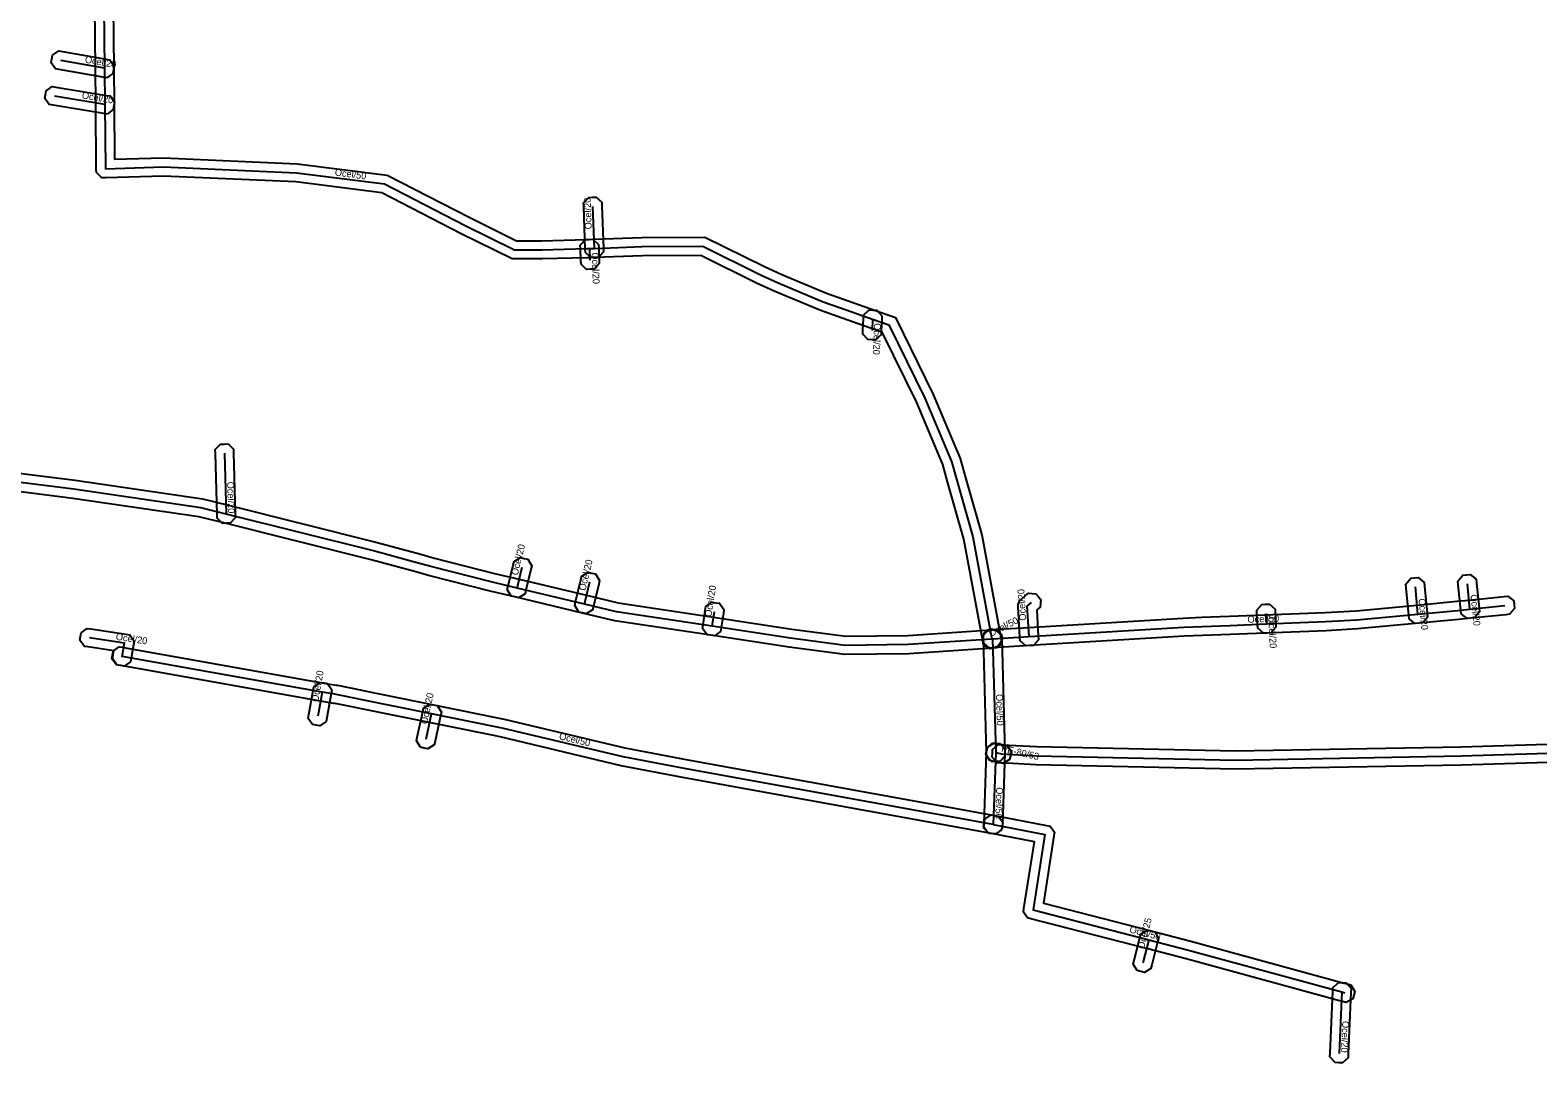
# Model space of a CAD drawing. Extents: x -569373 to -565022, y -1135090 to -1131496.
# Drawn here: x -566970.9 to -566806.1, y -1134199.3 to -1134085 of the extents above; entities that cross this region are included whole.
import ezdxf

# ---------------------------------------------------------------- set-up
doc = ezdxf.new("R2010")
doc.units = 0
for name, color, linetype in [('1', 7, 'Continuous'), ('24', 7, 'Continuous'), ('30', 7, 'Continuous')]:
    doc.layers.add(name, color=color, linetype=linetype)

msp = doc.modelspace()

# ---------------------------------------------------------------- linework, layer by layer
at = {"layer": '1'}
for points in [[(-566961.86, -1134082.458), (-566961.8, -1134089.11), (-566961.76, -1134093.061), (-566961.709, -1134099.068), (-566956.343, -1134098.899), (-566941.725, -1134099.553), (-566931.889, -1134100.79), (-566922.909, -1134105.417), (-566917.746, -1134107.97), (-566914.973, -1134107.97), (-566910.128, -1134107.84), (-566909.794, -1134107.831), (-566909.268, -1134107.811), (-566904.021, -1134107.61), (-566897.138, -1134107.579), (-566890.627, -1134110.798), (-566888.747, -1134111.674), (-566883.841, -1134113.706), (-566881.976, -1134114.367), (-566878.476, -1134115.607), (-566876.312, -1134116.373), (-566872.189, -1134124.776), (-566869.245, -1134131.788), (-566868.68, -1134133.767), (-566866.866, -1134140.131), (-566864.777, -1134151.337), (-566864.701, -1134151.744), (-566865.17, -1134152.427), (-566865.577, -1134152.503), (-566865.984, -1134152.579), (-566866.667, -1134152.11), (-566866.743, -1134151.703), (-566868.814, -1134140.589), (-566870.604, -1134134.315), (-566871.135, -1134132.452), (-566874.011, -1134125.604), (-566877.748, -1134117.987), (-566879.144, -1134117.493), (-566882.644, -1134116.253), (-566884.559, -1134115.574), (-566889.553, -1134113.506), (-566891.493, -1134112.602), (-566897.602, -1134109.581), (-566903.979, -1134109.61), (-566909.192, -1134109.809), (-566909.726, -1134109.829), (-566910.072, -1134109.84), (-566914.947, -1134109.97), (-566918.214, -1134109.97), (-566923.811, -1134107.203), (-566932.491, -1134102.73), (-566941.895, -1134101.547), (-566956.357, -1134100.901), (-566962.669, -1134101.1), (-566963.089, -1134101.113), (-566963.393, -1134100.821), (-566963.696, -1134100.529), (-566963.7, -1134100.109), (-566963.76, -1134093.079), (-566963.8, -1134089.13), (-566963.86, -1134082.402)], [(-566978.575, -1134132.578), (-566966.016, -1134134.159), (-566952.086, -1134136.178), (-566949.257, -1134136.89), (-566933.127, -1134140.922), (-566928.628, -1134142.149), (-566926.706, -1134142.673), (-566920.141, -1134144.339), (-566917.459, -1134144.977), (-566910.079, -1134146.727), (-566906.619, -1134147.548), (-566896.2, -1134149.131), (-566887.639, -1134150.43), (-566881.73, -1134151.219), (-566874.94, -1134151.13), (-566865.827, -1134150.522), (-566865.414, -1134150.495), (-566864.79, -1134151.04), (-566864.762, -1134151.453), (-566864.735, -1134151.866), (-566865.28, -1134152.49), (-566865.693, -1134152.518), (-566874.86, -1134153.13), (-566881.85, -1134153.221), (-566887.921, -1134152.41), (-566896.5, -1134151.109), (-566907.001, -1134149.512), (-566910.541, -1134148.673), (-566917.921, -1134146.923), (-566920.619, -1134146.281), (-566927.214, -1134144.607), (-566929.154, -1134144.079), (-566933.633, -1134142.858), (-566949.743, -1134138.83), (-566952.474, -1134138.142), (-566966.284, -1134136.141), (-566978.825, -1134134.562)], [(-566794.367, -1134164.679), (-566814.395, -1134165.3), (-566839.132, -1134165.75), (-566860.969, -1134165.279), (-566864.756, -1134165.068), (-566865.169, -1134165.045), (-566865.721, -1134164.428), (-566865.698, -1134164.014), (-566865.675, -1134163.601), (-566865.058, -1134163.049), (-566864.644, -1134163.072), (-566860.891, -1134163.281), (-566839.128, -1134163.75), (-566814.445, -1134163.3), (-566794.433, -1134162.681)]]:
    msp.add_lwpolyline(points, dxfattribs=at)
for points in [[(-566962.565, -1134090.177), (-566962.973, -1134090.105), (-566967.743, -1134089.265), (-566968.151, -1134089.193), (-566968.627, -1134088.515), (-566968.555, -1134088.107), (-566968.483, -1134087.699), (-566967.805, -1134087.223), (-566967.397, -1134087.295), (-566962.627, -1134088.135), (-566962.219, -1134088.207), (-566961.743, -1134088.885), (-566961.815, -1134089.293), (-566961.887, -1134089.701)], [(-566962.512, -1134094.124), (-566962.921, -1134094.057), (-566968.431, -1134093.157), (-566968.84, -1134093.09), (-566969.324, -1134092.418), (-566969.257, -1134092.009), (-566969.19, -1134091.6), (-566968.518, -1134091.116), (-566968.109, -1134091.183), (-566962.599, -1134092.083), (-566962.19, -1134092.15), (-566961.706, -1134092.822), (-566961.773, -1134093.231), (-566961.84, -1134093.64)], [(-566910.214, -1134109.261), (-566910.229, -1134108.847), (-566910.399, -1134104.257), (-566910.414, -1134103.843), (-566909.851, -1134103.236), (-566909.437, -1134103.221), (-566909.023, -1134103.206), (-566908.416, -1134103.769), (-566908.401, -1134104.183), (-566908.231, -1134108.773), (-566908.216, -1134109.187), (-566908.779, -1134109.794), (-566909.193, -1134109.809), (-566909.607, -1134109.824)], [(-566908.777, -1134108.377), (-566908.761, -1134108.791), (-566908.711, -1134110.061), (-566908.694, -1134110.475), (-566909.257, -1134111.083), (-566909.671, -1134111.099), (-566910.085, -1134111.116), (-566910.693, -1134110.553), (-566910.709, -1134110.139), (-566910.759, -1134108.869), (-566910.776, -1134108.455), (-566910.213, -1134107.847), (-566909.799, -1134107.831), (-566909.385, -1134107.814)], [(-566877.794, -1134116.176), (-566877.811, -1134116.59), (-566877.861, -1134117.84), (-566877.878, -1134118.254), (-566878.486, -1134118.816), (-566878.9, -1134118.799), (-566879.314, -1134118.782), (-566879.876, -1134118.174), (-566879.859, -1134117.76), (-566879.809, -1134116.51), (-566879.792, -1134116.096), (-566879.184, -1134115.534), (-566878.77, -1134115.551), (-566878.356, -1134115.568)], [(-566948.691, -1134130.759), (-566948.68, -1134131.173), (-566948.5, -1134137.833), (-566948.489, -1134138.247), (-566949.059, -1134138.849), (-566949.473, -1134138.86), (-566949.887, -1134138.871), (-566950.489, -1134138.301), (-566950.5, -1134137.887), (-566950.68, -1134131.227), (-566950.691, -1134130.813), (-566950.121, -1134130.211), (-566949.707, -1134130.2), (-566949.293, -1134130.189)], [(-566918.759, -1134146.118), (-566918.662, -1134145.715), (-566918.112, -1134143.435), (-566918.015, -1134143.032), (-566917.308, -1134142.601), (-566916.905, -1134142.698), (-566916.502, -1134142.795), (-566916.071, -1134143.502), (-566916.168, -1134143.905), (-566916.718, -1134146.185), (-566916.815, -1134146.588), (-566917.522, -1134147.019), (-566917.925, -1134146.922), (-566918.328, -1134146.825)], [(-566911.379, -1134147.87), (-566911.282, -1134147.467), (-566910.702, -1134145.047), (-566910.605, -1134144.644), (-566909.9, -1134144.211), (-566909.497, -1134144.308), (-566909.094, -1134144.405), (-566908.661, -1134145.11), (-566908.758, -1134145.513), (-566909.338, -1134147.933), (-566909.435, -1134148.336), (-566910.14, -1134148.769), (-566910.543, -1134148.672), (-566910.946, -1134148.575)], [(-566820.127, -1134149.306), (-566820.166, -1134148.894), (-566820.446, -1134145.924), (-566820.485, -1134145.511), (-566819.956, -1134144.873), (-566819.544, -1134144.834), (-566819.131, -1134144.795), (-566818.493, -1134145.324), (-566818.454, -1134145.736), (-566818.174, -1134148.706), (-566818.135, -1134149.119), (-566818.664, -1134149.757), (-566819.076, -1134149.796), (-566819.489, -1134149.835)], [(-566814.433, -1134148.763), (-566814.475, -1134148.351), (-566814.755, -1134145.601), (-566814.797, -1134145.189), (-566814.273, -1134144.547), (-566813.861, -1134144.505), (-566813.449, -1134144.463), (-566812.807, -1134144.987), (-566812.765, -1134145.399), (-566812.485, -1134148.149), (-566812.443, -1134148.561), (-566812.967, -1134149.203), (-566813.379, -1134149.245), (-566813.791, -1134149.287)], [(-566862.663, -1134151.713), (-566862.688, -1134151.3), (-566862.888, -1134147.98), (-566862.902, -1134147.744), (-566862.716, -1134147.309), (-566862.535, -1134147.156), (-566862.085, -1134146.776), (-566861.769, -1134146.509), (-566860.943, -1134146.579), (-566860.676, -1134146.895), (-566860.409, -1134147.211), (-566860.479, -1134148.037), (-566860.795, -1134148.304), (-566860.862, -1134148.36), (-566860.692, -1134151.18), (-566860.667, -1134151.593), (-566861.217, -1134152.213), (-566861.63, -1134152.238), (-566862.043, -1134152.263)], [(-566897.401, -1134150.379), (-566897.339, -1134149.97), (-566897.099, -1134148.39), (-566897.036, -1134147.98), (-566896.369, -1134147.489), (-566895.96, -1134147.551), (-566895.55, -1134147.614), (-566895.059, -1134148.281), (-566895.121, -1134148.69), (-566895.361, -1134150.27), (-566895.424, -1134150.68), (-566896.091, -1134151.171), (-566896.5, -1134151.109), (-566896.91, -1134151.046)], [(-566866.153, -1134150.507), (-566865.74, -1134150.482), (-566861.75, -1134150.242), (-566844.829, -1134149.221), (-566842.818, -1134149.145), (-566839.788, -1134149.031), (-566829.309, -1134148.621), (-566825.915, -1134148.423), (-566819.263, -1134147.804), (-566814.899, -1134147.395), (-566813.583, -1134147.255), (-566809.751, -1134146.865), (-566809.339, -1134146.823), (-566808.697, -1134147.347), (-566808.655, -1134147.759), (-566808.613, -1134148.171), (-566809.137, -1134148.813), (-566809.549, -1134148.855), (-566813.377, -1134149.245), (-566814.701, -1134149.385), (-566819.077, -1134149.796), (-566825.765, -1134150.417), (-566829.211, -1134150.619), (-566839.712, -1134151.029), (-566842.742, -1134151.143), (-566844.731, -1134151.219), (-566861.63, -1134152.238), (-566865.62, -1134152.478), (-566866.033, -1134152.503), (-566866.653, -1134151.953), (-566866.678, -1134151.54), (-566866.703, -1134151.127)], [(-566834.797, -1134148.244), (-566834.775, -1134148.658), (-566834.713, -1134149.819), (-566834.691, -1134150.232), (-566835.245, -1134150.849), (-566835.659, -1134150.871), (-566836.072, -1134150.893), (-566836.689, -1134150.339), (-566836.711, -1134149.925), (-566836.773, -1134148.764), (-566836.795, -1134148.351), (-566836.241, -1134147.734), (-566835.827, -1134147.712), (-566835.414, -1134147.69)], [(-566961.928, -1134153.65), (-566961.854, -1134153.242), (-566961.777, -1134152.815), (-566964.59, -1134152.389), (-566964.999, -1134152.327), (-566965.491, -1134151.66), (-566965.429, -1134151.25), (-566965.367, -1134150.841), (-566964.7, -1134150.349), (-566964.29, -1134150.411), (-566960.46, -1134150.991), (-566960.042, -1134151.055), (-566959.797, -1134151.398), (-566959.551, -1134151.742), (-566959.626, -1134152.158), (-566959.886, -1134153.598), (-566959.96, -1134154.006), (-566960.64, -1134154.478), (-566961.048, -1134154.404), (-566961.456, -1134154.33)], [(-566866.578, -1134150.811), (-566866.207, -1134150.626), (-566866.127, -1134150.586), (-566865.757, -1134150.4), (-566864.971, -1134150.662), (-566864.786, -1134151.033), (-566864.6, -1134151.403), (-566864.862, -1134152.189), (-566865.233, -1134152.374), (-566865.313, -1134152.414), (-566865.683, -1134152.6), (-566866.469, -1134152.338), (-566866.654, -1134151.967), (-566866.84, -1134151.597)], [(-566864.692, -1134151.039), (-566864.68, -1134151.453), (-566864.34, -1134163.893), (-566864.329, -1134164.307), (-566864.899, -1134164.908), (-566865.313, -1134164.92), (-566865.727, -1134164.931), (-566866.328, -1134164.361), (-566866.34, -1134163.947), (-566866.68, -1134151.507), (-566866.691, -1134151.093), (-566866.121, -1134150.492), (-566865.707, -1134150.48), (-566865.293, -1134150.469)], [(-566865.38, -1134172.858), (-566865.788, -1134172.784), (-566899.363, -1134166.703), (-566906.31, -1134165.378), (-566919.527, -1134162.226), (-566920.239, -1134162.08), (-566935.248, -1134159.056), (-566935.388, -1134159.006), (-566937.595, -1134158.563), (-566937.724, -1134158.554), (-566939.175, -1134158.294), (-566961.028, -1134154.408), (-566961.081, -1134154.4), (-566961.491, -1134154.342), (-566961.988, -1134153.679), (-566961.93, -1134153.269), (-566961.872, -1134152.859), (-566961.209, -1134152.362), (-566960.799, -1134152.42), (-566960.712, -1134152.432), (-566938.825, -1134156.326), (-566937.476, -1134156.566), (-566937.325, -1134156.577), (-566934.852, -1134157.074), (-566934.712, -1134157.124), (-566919.841, -1134160.12), (-566919.093, -1134160.274), (-566905.89, -1134163.422), (-566898.997, -1134164.737), (-566865.432, -1134170.816), (-566865.024, -1134170.89), (-566864.552, -1134171.57), (-566864.626, -1134171.978), (-566864.7, -1134172.386)], [(-566937.943, -1134157.077), (-566938.015, -1134157.485), (-566938.485, -1134160.135), (-566938.557, -1134160.543), (-566939.237, -1134161.017), (-566939.645, -1134160.945), (-566940.053, -1134160.873), (-566940.527, -1134160.193), (-566940.455, -1134159.785), (-566939.985, -1134157.135), (-566939.913, -1134156.727), (-566939.233, -1134156.253), (-566938.825, -1134156.325), (-566938.417, -1134156.397)], [(-566928.694, -1134162.656), (-566928.606, -1134162.251), (-566928.004, -1134159.48), (-566927.916, -1134159.075), (-566927.22, -1134158.627), (-566926.815, -1134158.715), (-566926.41, -1134158.803), (-566925.962, -1134159.499), (-566926.05, -1134159.904), (-566926.652, -1134162.675), (-566926.74, -1134163.08), (-566927.436, -1134163.528), (-566927.841, -1134163.44), (-566928.246, -1134163.352)], [(-566864.327, -1134163.54), (-566864.341, -1134163.954), (-566864.611, -1134171.834), (-566864.625, -1134172.248), (-566865.23, -1134172.813), (-566865.644, -1134172.799), (-566866.058, -1134172.785), (-566866.623, -1134172.18), (-566866.609, -1134171.766), (-566866.339, -1134163.886), (-566866.325, -1134163.472), (-566865.72, -1134162.907), (-566865.306, -1134162.921), (-566864.892, -1134162.935)], [(-566865.515, -1134162.852), (-566865.112, -1134162.946), (-566864.472, -1134163.096), (-566864.069, -1134163.191), (-566863.632, -1134163.895), (-566863.726, -1134164.298), (-566863.821, -1134164.701), (-566864.525, -1134165.138), (-566864.928, -1134165.044), (-566865.568, -1134164.894), (-566865.971, -1134164.799), (-566866.408, -1134164.095), (-566866.314, -1134163.692), (-566866.219, -1134163.289)], [(-566865.831, -1134170.74), (-566865.424, -1134170.817), (-566859.774, -1134171.887), (-566859.376, -1134171.963), (-566858.909, -1134172.625), (-566858.972, -1134173.025), (-566860.131, -1134180.398), (-566848.35, -1134183.432), (-566844.013, -1134184.553), (-566827.227, -1134189.125), (-566826.897, -1134189.215), (-566826.497, -1134189.324), (-566826.086, -1134190.043), (-566826.195, -1134190.443), (-566826.304, -1134190.843), (-566827.023, -1134191.254), (-566827.423, -1134191.145), (-566827.753, -1134191.055), (-566844.527, -1134186.487), (-566848.85, -1134185.368), (-566861.509, -1134182.108), (-566861.883, -1134182.012), (-566862.308, -1134181.367), (-566862.248, -1134180.985), (-566861.098, -1134173.672), (-566865.796, -1134172.783), (-566866.203, -1134172.706), (-566866.67, -1134172.021), (-566866.593, -1134171.614), (-566866.516, -1134171.207)], [(-566847.528, -1134184.247), (-566847.631, -1134184.648), (-566848.271, -1134187.148), (-566848.374, -1134187.549), (-566849.087, -1134187.972), (-566849.488, -1134187.869), (-566849.889, -1134187.766), (-566850.312, -1134187.053), (-566850.209, -1134186.652), (-566849.569, -1134184.152), (-566849.466, -1134183.751), (-566848.753, -1134183.328), (-566848.352, -1134183.431), (-566847.951, -1134183.534)], [(-566826.473, -1134189.719), (-566826.491, -1134190.133), (-566826.781, -1134196.883), (-566826.799, -1134197.297), (-566827.409, -1134197.857), (-566827.823, -1134197.839), (-566828.237, -1134197.821), (-566828.797, -1134197.211), (-566828.779, -1134196.797), (-566828.489, -1134190.047), (-566828.471, -1134189.633), (-566827.861, -1134189.073), (-566827.447, -1134189.091), (-566827.033, -1134189.109)]]:
    msp.add_lwpolyline(points, close=True, dxfattribs=at)
at = {"layer": '24'}
for points in [[(-566962.86, -1134082.43), (-566962.8, -1134089.12), (-566962.76, -1134093.07), (-566962.7, -1134100.1), (-566956.35, -1134099.9), (-566941.81, -1134100.55), (-566932.19, -1134101.76), (-566923.36, -1134106.31), (-566917.98, -1134108.97), (-566914.96, -1134108.97), (-566910.1, -1134108.84), (-566909.76, -1134108.83), (-566909.23, -1134108.81), (-566904, -1134108.61), (-566897.37, -1134108.58), (-566891.06, -1134111.7), (-566889.15, -1134112.59), (-566884.2, -1134114.64), (-566882.31, -1134115.31), (-566878.81, -1134116.55), (-566877.03, -1134117.18), (-566873.1, -1134125.19), (-566870.19, -1134132.12), (-566869.642, -1134134.041), (-566867.84, -1134140.36), (-566865.76, -1134151.52)], [(-566962.8, -1134089.12), (-566967.57, -1134088.28)], [(-566962.76, -1134093.07), (-566968.27, -1134092.17)], [(-566909.23, -1134108.81), (-566909.4, -1134104.22)], [(-566909.76, -1134108.83), (-566909.71, -1134110.1)], [(-566878.81, -1134116.55), (-566878.86, -1134117.8)], [(-566949.68, -1134131.2), (-566949.5, -1134137.86)], [(-566865.76, -1134151.52), (-566874.9, -1134152.13), (-566881.79, -1134152.22), (-566887.78, -1134151.42), (-566896.35, -1134150.12), (-566906.81, -1134148.53), (-566910.31, -1134147.7), (-566917.69, -1134145.95), (-566920.38, -1134145.31), (-566926.96, -1134143.64), (-566928.891, -1134143.114), (-566933.38, -1134141.89), (-566949.5, -1134137.86), (-566952.28, -1134137.16), (-566966.15, -1134135.15), (-566978.7, -1134133.57)], [(-566917.69, -1134145.95), (-566917.14, -1134143.67)], [(-566910.31, -1134147.7), (-566909.73, -1134145.28)], [(-566819.17, -1134148.8), (-566819.45, -1134145.83)], [(-566813.48, -1134148.25), (-566813.76, -1134145.5)], [(-566865.68, -1134151.48), (-566861.69, -1134151.24), (-566844.78, -1134150.22), (-566842.78, -1134150.144), (-566839.75, -1134150.03), (-566835.712, -1134149.872), (-566829.26, -1134149.62), (-566825.84, -1134149.42), (-566819.17, -1134148.8), (-566814.8, -1134148.39), (-566813.48, -1134148.25), (-566809.65, -1134147.86)], [(-566861.69, -1134151.24), (-566861.89, -1134147.92), (-566861.44, -1134147.54)], [(-566896.35, -1134150.12), (-566896.11, -1134148.54)], [(-566835.774, -1134148.711), (-566835.712, -1134149.872)], [(-566960.87, -1134153.42), (-566960.61, -1134151.98), (-566964.44, -1134151.4)], [(-566865.76, -1134151.52), (-566865.68, -1134151.48)], [(-566865.68, -1134151.48), (-566865.34, -1134163.92)], [(-566865.61, -1134171.8), (-566899.18, -1134165.72), (-566906.1, -1134164.4), (-566919.31, -1134161.25), (-566920.04, -1134161.1), (-566927.027, -1134159.692), (-566934.98, -1134158.09), (-566935.12, -1134158.04), (-566937.46, -1134157.57), (-566937.6, -1134157.56), (-566939, -1134157.31), (-566960.87, -1134153.42), (-566960.94, -1134153.41)], [(-566939, -1134157.31), (-566939.47, -1134159.96)], [(-566927.629, -1134162.463), (-566927.027, -1134159.692)], [(-566864.7, -1134164.07), (-566860.93, -1134164.28), (-566839.13, -1134164.75), (-566814.42, -1134164.3), (-566794.4, -1134163.68), (-566780.58, -1134163.2), (-566758.96, -1134161.71), (-566755.58, -1134161.33), (-566753.53, -1134161.36), (-566752.04, -1134161.92), (-566750.69, -1134163.31), (-566749.78, -1134164.99), (-566748.5, -1134168.08), (-566746.44, -1134171.65), (-566739.81, -1134179.97), (-566725.47, -1134196.03), (-566715.83, -1134207.38)], [(-566865.34, -1134163.92), (-566865.61, -1134171.8)], [(-566865.34, -1134163.92), (-566864.7, -1134164.07)], [(-566865.61, -1134171.8), (-566859.96, -1134172.87), (-566861.26, -1134181.14), (-566848.6, -1134184.4), (-566844.27, -1134185.52), (-566827.49, -1134190.09), (-566827.16, -1134190.18)], [(-566848.6, -1134184.4), (-566849.24, -1134186.9)], [(-566827.49, -1134190.09), (-566827.78, -1134196.84)]]:
    msp.add_lwpolyline(points, dxfattribs=at)

# ---------------------------------------------------------------- texts
at = {"layer": '30'}
for s, rotation, p in [('Ocel/20', 350.01258, (-566964.985, -1134088.5)), ('Ocel/20', 350.72326, (-566965.315, -1134092.42)), ('Ocel/50', 352.83101, (-566937.646, -1134100.849)), ('Ocel/20', 92.1211, (-566909.515, -1134106.715)), ('Ocel/20', 272.25457, (-566909.535, -1134109.265)), ('Ocel/20', 267.70939, (-566878.635, -1134116.975)), ('Ocel/20', 271.54816, (-566949.39, -1134134.33)), ('Ocel/20', 76.43775, (-566917.615, -1134144.61)), ('Ocel/20', 76.52218, (-566910.22, -1134146.29)), ('Ocel/20', 81.36287, (-566896.43, -1134149.13)), ('Ocel/20', 93.44739, (-566862.008, -1134149.486)), ('Ocel/20', 275.81372, (-566813.42, -1134146.675)), ('Ocel/20', 275.3857, (-566819.11, -1134147.115)), ('Ocel/50', 26.56505, (-566865.875, -1134151.278)), ('Ocel/50', 2.24074, (-566837.793, -1134149.746)), ('Ocel/20', 273.05682, (-566835.543, -1134149.092)), ('Ocel/20', 351.38878, (-566961.602, -1134151.6)), ('Ocel/20', 79.94269, (-566939.435, -1134158.435)), ('Ocel/20', 77.74295, (-566927.528, -1134160.878)), ('Ocel/50', 271.56557, (-566865.309, -1134157.55)), ('Ocel/50', 346.58796, (-566913.14, -1134162.473)), ('PE-80/63', 346.80939, (-566864.771, -1134163.806)), ('Ocel/50', 268.03759, (-566865.277, -1134167.71)), ('Ocel/50', 345.55982, (-566850.767, -1134183.59)), ('Ocel/25', 75.64066, (-566849.12, -1134185.45)), ('Ocel/20', 267.53992, (-566827.435, -1134193.265))]:
    msp.add_text(s, height=0.75, rotation=rotation, dxfattribs=at).set_placement(p)

doc.saveas('drawing.dxf')
